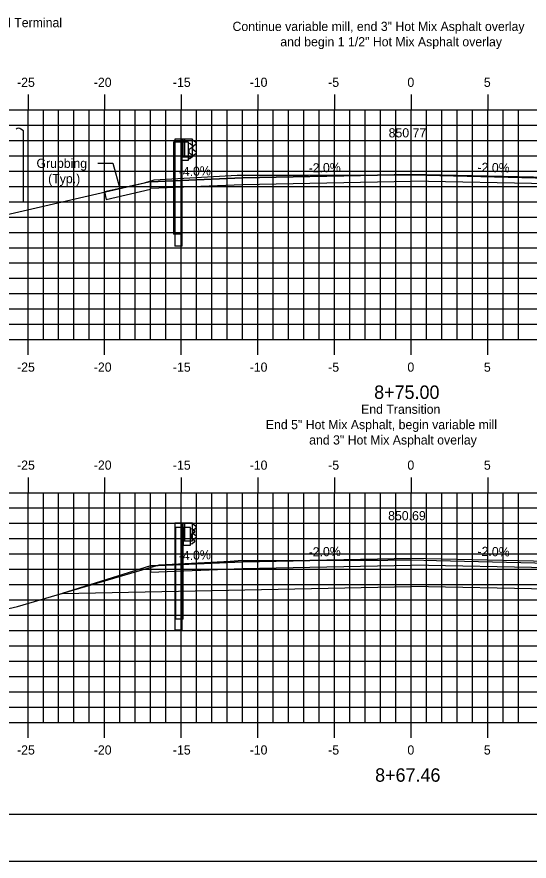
# Model space of a CAD drawing. Extents: x 2194502 to 2194968, y 863888 to 863998.
# Drawn here: x 2194672.8 to 2194706.2, y 863888.4 to 863943.5 of the extents above; entities that cross this region are included whole.
import ezdxf

# ---------------------------------------------------------------- set-up
doc = ezdxf.new("R2010")
doc.units = 0
for name, color, linetype in [('ANNOTATION', 7, 'Continuous'), ('BORDER', 7, 'Continuous'), ('D_Guardrail_Beam_Lt', 7, 'Continuous'), ('D_Guardrail_Beam_Rt', 7, 'Continuous'), ('H_V ANNOTATION', 7, 'Continuous'), ('MAJOR', 7, 'Continuous'), ('MINOR', 7, 'Continuous'), ('PLOT BOUNDARY', 7, 'Continuous'), ('S_Guardrail_Beam', 7, 'Continuous'), ('S_Roadway_Centerline', 7, 'Continuous'), ('S_Utilities_Pole_Power', 7, 'Continuous'), ('TEMPLATE', 7, 'Continuous')]:
    doc.layers.add(name, color=color, linetype=linetype)

msp = doc.modelspace()

# ---------------------------------------------------------------- linework, layer by layer
at = {"layer": 'ANNOTATION'}
msp.add_lwpolyline([(2194678.045, 863933.956), (2194679.045, 863933.956), (2194679.486, 863932.307)], dxfattribs=at)
at = {"layer": 'BORDER'}
msp.add_lwpolyline([(2194623.499, 863891.446), (2194783.499, 863891.446), (2194783.499, 863996.446), (2194623.499, 863996.446)], close=True, dxfattribs=at)
at = {"layer": 'D_Guardrail_Beam_Lt'}
for p, q in [((2194683.07, 863935.542), (2194683.07, 863928.542)), ((2194683.541, 863935.542), (2194683.07, 863935.542)), ((2194684.228, 863935.542), (2194683.541, 863935.542)), ((2194683.541, 863935.542), (2194683.541, 863934.376)), ((2194683.603, 863935.542), (2194683.603, 863934.376)), ((2194683.708, 863935.542), (2194683.708, 863934.376)), ((2194684.228, 863934.376), (2194684.228, 863935.542)), ((2194684.228, 863935.459), (2194684.303, 863935.445)), ((2194684.233, 863934.994), (2194684.233, 863934.924)), ((2194684.462, 863935.195), (2194684.267, 863935.059)), ((2194684.318, 863935.438), (2194684.462, 863935.338)), ((2194683.541, 863934.376), (2194684.228, 863934.376)), ((2194683.562, 863928.542), (2194683.562, 863934.376)), ((2194684.303, 863934.474), (2194684.228, 863934.459)), ((2194684.267, 863934.86), (2194684.462, 863934.723)), ((2194684.462, 863934.58), (2194684.318, 863934.48)), ((2194683.562, 863928.542), (2194683.07, 863928.542))]:
    msp.add_line(p, q, dxfattribs=at)
for centre, major_axis, start_param, end_param in [((2194684.312, 863934.994), (-0.0789, 0), 5.323254, 6.283185), ((2194684.312, 863934.924), (-0.0789, 0), 6.283185, 7.243116), ((2194684.295, 863935.404), (0.0417, 0), 0.959931, 1.376053), ((2194684.412, 863935.266), (0.0877, 0), 5.323254, 7.243116), ((2194684.295, 863934.514), (0.0417, 0), 4.907132, 5.323254), ((2194684.412, 863934.652), (0.0877, 0), 5.323254, 7.243116)]:
    msp.add_ellipse(centre, major_axis=major_axis, ratio=0.995501, start_param=start_param, end_param=end_param, dxfattribs=at)
at = {"layer": 'D_Guardrail_Beam_Rt'}
for p, q in [((2194683.07, 863910.466), (2194683.07, 863903.466)), ((2194683.541, 863910.466), (2194683.07, 863910.466)), ((2194684.228, 863910.466), (2194683.541, 863910.466)), ((2194683.541, 863910.466), (2194683.541, 863909.3)), ((2194683.603, 863910.466), (2194683.603, 863909.3)), ((2194683.708, 863910.466), (2194683.708, 863909.3)), ((2194684.228, 863909.3), (2194684.228, 863910.466)), ((2194684.228, 863910.383), (2194684.303, 863910.368)), ((2194684.462, 863910.119), (2194684.267, 863909.982)), ((2194684.318, 863910.362), (2194684.462, 863910.262)), ((2194684.233, 863909.918), (2194684.233, 863909.848)), ((2194684.267, 863909.783), (2194684.462, 863909.647)), ((2194683.541, 863909.3), (2194684.228, 863909.3)), ((2194683.562, 863903.466), (2194683.562, 863909.3)), ((2194684.303, 863909.397), (2194684.228, 863909.383)), ((2194684.462, 863909.504), (2194684.318, 863909.404)), ((2194683.562, 863903.466), (2194683.07, 863903.466))]:
    msp.add_line(p, q, dxfattribs=at)
for centre, major_axis, start_param, end_param in [((2194684.295, 863910.328), (0.0417, 0), 0.959931, 1.376053), ((2194684.412, 863910.19), (0.0877, 0), 5.323254, 7.243116), ((2194684.312, 863909.918), (-0.0789, 0), 5.323254, 6.283185), ((2194684.312, 863909.848), (-0.0789, 0), 6.283185, 7.243116), ((2194684.412, 863909.576), (0.0877, 0), 5.323254, 7.243116), ((2194684.295, 863909.438), (0.0417, 0), 4.907132, 5.323254)]:
    msp.add_ellipse(centre, major_axis=major_axis, ratio=0.995501, start_param=start_param, end_param=end_param, dxfattribs=at)
at = {"layer": 'MAJOR'}
for p, q in [((2194673.499, 863938.448), (2194673.499, 863937.446)), ((2194678.499, 863938.448), (2194678.499, 863937.446)), ((2194683.499, 863938.448), (2194683.499, 863937.446)), ((2194688.499, 863938.448), (2194688.499, 863937.446)), ((2194693.499, 863938.448), (2194693.499, 863937.446)), ((2194698.499, 863938.448), (2194698.499, 863937.446)), ((2194703.499, 863938.448), (2194703.499, 863937.446)), ((2194628.499, 863937.446), (2194768.499, 863937.446)), ((2194673.499, 863922.446), (2194673.499, 863937.446)), ((2194678.499, 863922.446), (2194678.499, 863937.446)), ((2194683.499, 863922.446), (2194683.499, 863937.446)), ((2194688.499, 863922.446), (2194688.499, 863937.446)), ((2194693.499, 863922.446), (2194693.499, 863937.446)), ((2194698.499, 863922.446), (2194698.499, 863937.446)), ((2194703.499, 863922.446), (2194703.499, 863937.446)), ((2194628.499, 863932.446), (2194768.499, 863932.446)), ((2194628.499, 863927.446), (2194768.499, 863927.446)), ((2194628.499, 863922.446), (2194768.499, 863922.446)), ((2194673.499, 863921.444), (2194673.499, 863922.446)), ((2194678.499, 863921.444), (2194678.499, 863922.446)), ((2194683.499, 863921.444), (2194683.499, 863922.446)), ((2194688.499, 863921.444), (2194688.499, 863922.446)), ((2194693.499, 863921.444), (2194693.499, 863922.446)), ((2194698.499, 863921.444), (2194698.499, 863922.446)), ((2194703.499, 863921.444), (2194703.499, 863922.446)), ((2194673.499, 863913.448), (2194673.499, 863912.446)), ((2194678.499, 863913.448), (2194678.499, 863912.446)), ((2194683.499, 863913.448), (2194683.499, 863912.446)), ((2194688.499, 863913.448), (2194688.499, 863912.446)), ((2194693.499, 863913.448), (2194693.499, 863912.446)), ((2194698.499, 863913.448), (2194698.499, 863912.446)), ((2194703.499, 863913.448), (2194703.499, 863912.446)), ((2194628.499, 863912.446), (2194768.499, 863912.446)), ((2194673.499, 863897.446), (2194673.499, 863912.446)), ((2194678.499, 863897.446), (2194678.499, 863912.446)), ((2194683.499, 863897.446), (2194683.499, 863912.446)), ((2194688.499, 863897.446), (2194688.499, 863912.446)), ((2194693.499, 863897.446), (2194693.499, 863912.446)), ((2194698.499, 863897.446), (2194698.499, 863912.446)), ((2194703.499, 863897.446), (2194703.499, 863912.446)), ((2194628.499, 863907.446), (2194768.499, 863907.446)), ((2194628.499, 863902.446), (2194768.499, 863902.446)), ((2194628.499, 863897.446), (2194768.499, 863897.446)), ((2194673.499, 863896.444), (2194673.499, 863897.446)), ((2194678.499, 863896.444), (2194678.499, 863897.446)), ((2194683.499, 863896.444), (2194683.499, 863897.446)), ((2194688.499, 863896.444), (2194688.499, 863897.446)), ((2194693.499, 863896.444), (2194693.499, 863897.446)), ((2194698.499, 863896.444), (2194698.499, 863897.446)), ((2194703.499, 863896.444), (2194703.499, 863897.446))]:
    msp.add_line(p, q, dxfattribs=at)
at = {"layer": 'MINOR'}
for p, q in [((2194674.499, 863922.446), (2194674.499, 863937.446)), ((2194675.499, 863922.446), (2194675.499, 863937.446)), ((2194676.499, 863922.446), (2194676.499, 863937.446)), ((2194677.499, 863922.446), (2194677.499, 863937.446)), ((2194679.499, 863922.446), (2194679.499, 863937.446)), ((2194680.499, 863922.446), (2194680.499, 863937.446)), ((2194681.499, 863922.446), (2194681.499, 863937.446)), ((2194682.499, 863922.446), (2194682.499, 863937.446)), ((2194684.499, 863922.446), (2194684.499, 863937.446)), ((2194685.499, 863922.446), (2194685.499, 863937.446)), ((2194686.499, 863922.446), (2194686.499, 863937.446)), ((2194687.499, 863922.446), (2194687.499, 863937.446)), ((2194689.499, 863922.446), (2194689.499, 863937.446)), ((2194690.499, 863922.446), (2194690.499, 863937.446)), ((2194691.499, 863922.446), (2194691.499, 863937.446)), ((2194692.499, 863922.446), (2194692.499, 863937.446)), ((2194694.499, 863922.446), (2194694.499, 863937.446)), ((2194695.499, 863922.446), (2194695.499, 863937.446)), ((2194696.499, 863922.446), (2194696.499, 863937.446)), ((2194697.499, 863922.446), (2194697.499, 863937.446)), ((2194699.499, 863922.446), (2194699.499, 863937.446)), ((2194700.499, 863922.446), (2194700.499, 863937.446)), ((2194701.499, 863922.446), (2194701.499, 863937.446)), ((2194702.499, 863922.446), (2194702.499, 863937.446)), ((2194704.499, 863922.446), (2194704.499, 863937.446)), ((2194705.499, 863922.446), (2194705.499, 863937.446)), ((2194628.499, 863936.446), (2194768.499, 863936.446)), ((2194628.499, 863935.446), (2194768.499, 863935.446)), ((2194628.499, 863934.446), (2194768.499, 863934.446)), ((2194628.499, 863933.446), (2194768.499, 863933.446)), ((2194628.499, 863931.446), (2194768.499, 863931.446)), ((2194628.499, 863930.446), (2194768.499, 863930.446)), ((2194628.499, 863929.446), (2194768.499, 863929.446)), ((2194628.499, 863928.446), (2194768.499, 863928.446)), ((2194628.499, 863926.446), (2194768.499, 863926.446)), ((2194628.499, 863925.446), (2194768.499, 863925.446)), ((2194628.499, 863924.446), (2194768.499, 863924.446)), ((2194628.499, 863923.446), (2194768.499, 863923.446)), ((2194674.499, 863897.446), (2194674.499, 863912.446)), ((2194675.499, 863897.446), (2194675.499, 863912.446)), ((2194676.499, 863897.446), (2194676.499, 863912.446)), ((2194677.499, 863897.446), (2194677.499, 863912.446)), ((2194679.499, 863897.446), (2194679.499, 863912.446)), ((2194680.499, 863897.446), (2194680.499, 863912.446)), ((2194681.499, 863897.446), (2194681.499, 863912.446)), ((2194682.499, 863897.446), (2194682.499, 863912.446)), ((2194684.499, 863897.446), (2194684.499, 863912.446)), ((2194685.499, 863897.446), (2194685.499, 863912.446)), ((2194686.499, 863897.446), (2194686.499, 863912.446)), ((2194687.499, 863897.446), (2194687.499, 863912.446)), ((2194689.499, 863897.446), (2194689.499, 863912.446)), ((2194690.499, 863897.446), (2194690.499, 863912.446)), ((2194691.499, 863897.446), (2194691.499, 863912.446)), ((2194692.499, 863897.446), (2194692.499, 863912.446)), ((2194694.499, 863897.446), (2194694.499, 863912.446)), ((2194695.499, 863897.446), (2194695.499, 863912.446)), ((2194696.499, 863897.446), (2194696.499, 863912.446)), ((2194697.499, 863897.446), (2194697.499, 863912.446)), ((2194699.499, 863897.446), (2194699.499, 863912.446)), ((2194700.499, 863897.446), (2194700.499, 863912.446)), ((2194701.499, 863897.446), (2194701.499, 863912.446)), ((2194702.499, 863897.446), (2194702.499, 863912.446)), ((2194704.499, 863897.446), (2194704.499, 863912.446)), ((2194705.499, 863897.446), (2194705.499, 863912.446)), ((2194628.499, 863911.446), (2194768.499, 863911.446)), ((2194628.499, 863910.446), (2194768.499, 863910.446)), ((2194628.499, 863909.446), (2194768.499, 863909.446)), ((2194628.499, 863908.446), (2194768.499, 863908.446)), ((2194628.499, 863906.446), (2194768.499, 863906.446)), ((2194628.499, 863905.446), (2194768.499, 863905.446)), ((2194628.499, 863904.446), (2194768.499, 863904.446)), ((2194628.499, 863903.446), (2194768.499, 863903.446)), ((2194628.499, 863901.446), (2194768.499, 863901.446)), ((2194628.499, 863900.446), (2194768.499, 863900.446)), ((2194628.499, 863899.446), (2194768.499, 863899.446)), ((2194628.499, 863898.446), (2194768.499, 863898.446))]:
    msp.add_line(p, q, dxfattribs=at)
at = {"layer": 'PLOT BOUNDARY'}
msp.add_lwpolyline([(2194615.406, 863888.387), (2194785.406, 863888.387), (2194785.406, 863998.387), (2194615.406, 863998.387)], close=True, dxfattribs=at)
at = {"layer": 'S_Guardrail_Beam'}
for p, q in [((2194682.997, 863935.335), (2194682.997, 863929.335)), ((2194683.489, 863935.335), (2194682.997, 863935.335)), ((2194683.978, 863935.335), (2194683.489, 863935.335)), ((2194683.489, 863935.335), (2194683.489, 863934.168)), ((2194683.978, 863934.168), (2194683.978, 863935.335)), ((2194683.978, 863935.262), (2194684.06, 863935.248)), ((2194684.22, 863934.998), (2194684.025, 863934.861)), ((2194684.077, 863935.241), (2194684.22, 863935.141)), ((2194683.991, 863934.797), (2194683.991, 863934.706)), ((2194684.025, 863934.642), (2194684.22, 863934.506)), ((2194683.489, 863929.335), (2194683.489, 863934.168)), ((2194683.489, 863934.168), (2194683.978, 863934.168)), ((2194684.06, 863934.256), (2194683.978, 863934.241)), ((2194684.22, 863934.362), (2194684.077, 863934.262)), ((2194683.489, 863929.335), (2194682.997, 863929.335)), ((2194683.127, 863910.179), (2194683.127, 863904.179)), ((2194683.619, 863910.179), (2194683.127, 863910.179)), ((2194684.108, 863910.179), (2194683.619, 863910.179)), ((2194683.619, 863910.179), (2194683.619, 863909.012)), ((2194684.108, 863909.012), (2194684.108, 863910.179)), ((2194684.108, 863910.106), (2194684.191, 863910.091)), ((2194684.122, 863909.641), (2194684.122, 863909.55)), ((2194684.351, 863909.842), (2194684.155, 863909.705)), ((2194684.207, 863910.085), (2194684.351, 863909.985)), ((2194683.619, 863904.179), (2194683.619, 863909.012)), ((2194683.619, 863909.012), (2194684.108, 863909.012)), ((2194684.191, 863909.099), (2194684.108, 863909.085)), ((2194684.155, 863909.486), (2194684.351, 863909.349)), ((2194684.351, 863909.206), (2194684.207, 863909.106)), ((2194683.619, 863904.179), (2194683.127, 863904.179))]:
    msp.add_line(p, q, dxfattribs=at)
for centre, major_axis, start_param, end_param in [((2194684.053, 863935.207), (0.0417, 0), 0.959931, 1.396263), ((2194684.17, 863935.069), (0.0877, 0), 5.323254, 7.243116), ((2194684.07, 863934.797), (-0.0789, 0), 5.323254, 6.283185), ((2194684.07, 863934.706), (-0.0789, 0), 6.283185, 7.243116), ((2194684.17, 863934.434), (0.0877, 0), 5.323254, 7.243116), ((2194684.053, 863934.296), (0.0417, 0), 4.886922, 5.323254), ((2194684.201, 863909.641), (-0.0789, 0), 5.323254, 6.283185), ((2194684.183, 863910.051), (0.0417, 0), 0.959931, 1.396263), ((2194684.3, 863909.913), (0.0877, 0), 5.323254, 7.243116), ((2194684.201, 863909.55), (-0.0789, 0), 6.283185, 7.243116), ((2194684.183, 863909.14), (0.0417, 0), 4.886922, 5.323254), ((2194684.3, 863909.278), (0.0877, 0), 5.323254, 7.243116)]:
    msp.add_ellipse(centre, major_axis=major_axis, ratio=0.995501, start_param=start_param, end_param=end_param, dxfattribs=at)
at = {"layer": 'S_Roadway_Centerline'}
for points in [[(2194628.499, 863931.248), (2194644.102, 863931.812), (2194651.913, 863930.949), (2194668.077, 863929.672), (2194681.104, 863932.691), (2194681.74, 863932.878), (2194687.144, 863933.179), (2194687.162, 863933.181), (2194691.811, 863933.191), (2194698.499, 863933.212), (2194698.585, 863933.211), (2194710.18, 863932.915), (2194712.278, 863932.755), (2194712.76, 863932.719), (2194712.774, 863932.719), (2194718.053, 863932.454), (2194719.251, 863932.444), (2194722.99, 863932.169), (2194730.529, 863930.489), (2194735.351, 863929.559), (2194737.618, 863928.913), (2194750.8, 863926.104), (2194768.499, 863925.832)], [(2194667.598, 863903.809), (2194672.818, 863905.013), (2194682.058, 863907.726), (2194686.684, 863907.983), (2194687.208, 863908.025), (2194696.988, 863908.045), (2194698.48, 863908.066), (2194700.167, 863908.027), (2194710.222, 863907.77), (2194710.933, 863907.72), (2194713.063, 863907.563), (2194714.672, 863907.54), (2194718.844, 863907.33), (2194723.196, 863907.293), (2194725.536, 863907.121), (2194734.215, 863905.192), (2194736.558, 863903.65), (2194738.492, 863903.278), (2194745.923, 863901.819), (2194754.026, 863901.226), (2194762.901, 863901.073), (2194768.499, 863901.043)]]:
    msp.add_lwpolyline(points, dxfattribs=at)
at = {"layer": 'S_Utilities_Pole_Power'}
for p, q in [((2194673.195, 863936.084), (2194673.039, 863936.194)), ((2194673.195, 863931.464), (2194673.198, 863936.084))]:
    msp.add_line(p, q, dxfattribs=at)
for start, end in [(90, 125.2644), (54.7356, 90)]:
    msp.add_arc((2194672.882, 863935.973), 0.271, start, end, dxfattribs=at)
at = {"layer": 'TEMPLATE'}
for p, q in [((2194681.499, 863932.756), (2194678.499, 863932.088)), ((2194687.499, 863932.996), (2194681.499, 863932.756)), ((2194687.499, 863932.996), (2194698.499, 863933.216)), ((2194698.499, 863933.216), (2194687.499, 863932.996)), ((2194687.499, 863932.579), (2194698.499, 863932.799)), ((2194709.499, 863932.996), (2194698.499, 863933.216)), ((2194709.499, 863932.579), (2194698.499, 863932.799)), ((2194678.499, 863932.088), (2194678.608, 863931.6)), ((2194687.499, 863907.92), (2194681.499, 863907.68)), ((2194687.499, 863907.92), (2194698.499, 863908.14)), ((2194698.499, 863908.14), (2194687.499, 863907.92)), ((2194709.499, 863907.92), (2194698.499, 863908.14)), ((2194681.499, 863907.68), (2194675.727, 863905.867)), ((2194687.499, 863907.503), (2194698.499, 863907.723)), ((2194709.499, 863907.503), (2194698.499, 863907.723)), ((2194675.727, 863905.867), (2194698.499, 863906.323)), ((2194708.499, 863906.123), (2194698.499, 863906.323))]:
    msp.add_line(p, q, dxfattribs=at)
for points in [[(2194681.499, 863932.756), (2194681.499, 863932.756), (2194687.499, 863932.996)], [(2194681.499, 863932.339), (2194681.499, 863932.756), (2194681.499, 863932.339), (2194687.499, 863932.579)], [(2194678.608, 863931.6), (2194681.499, 863932.27), (2194681.499, 863932.339)], [(2194681.499, 863907.68), (2194681.499, 863907.68), (2194687.499, 863907.92)], [(2194681.499, 863907.263), (2194681.499, 863907.68), (2194681.499, 863907.263), (2194687.499, 863907.503)]]:
    msp.add_lwpolyline(points, dxfattribs=at)

# ---------------------------------------------------------------- texts
at = {"layer": 'ANNOTATION'}
for s, p in [('Install 31" W-Beam Guardrail, Mid-Way Splice Flared Terminal', (2194653.499, 863942.844)), ('Continue variable mill, end 3" Hot Mix Asphalt overlay', (2194686.845, 863942.596)), ('and begin 1 1/2" Hot Mix Asphalt overlay', (2194689.963, 863941.594)), ('850.77', (2194697.033, 863935.646)), ('Grubbing', (2194674.052, 863933.656)), ('(Typ.)', (2194674.812, 863932.654)), ('End Transition', (2194695.236, 863917.596)), ('End 5" Hot Mix Asphalt, begin variable mill', (2194689.018, 863916.594)), ('and 3" Hot Mix Asphalt overlay', (2194691.846, 863915.592)), ('850.69', (2194697.001, 863910.646))]:
    msp.add_text(s, height=0.6, dxfattribs=at).set_placement(p)
for s, rotation, p in [('-2.0%', 1.1458, (2194691.817, 863933.349)), ('-2.0%', 358.8542, (2194702.828, 863933.396)), ('-4.0%', 2.2906, (2194683.344, 863933.097)), ('-4.0%', 2.2906, (2194683.344, 863908.02)), ('-2.0%', 1.1458, (2194691.817, 863908.273)), ('-2.0%', 358.8542, (2194702.828, 863908.32))]:
    msp.add_text(s, height=0.6, rotation=rotation, dxfattribs=at).set_placement(p)
at = {"layer": 'H_V ANNOTATION'}
for s, height, p in [('-25', 0.6, (2194672.785, 863938.946)), ('-20', 0.6, (2194677.793, 863938.946)), ('-15', 0.6, (2194682.956, 863938.946)), ('-10', 0.6, (2194687.964, 863938.946)), ('-5', 0.6, (2194693.09, 863938.946)), ('0', 0.6, (2194698.258, 863938.946)), ('5', 0.6, (2194703.25, 863938.946)), ('-25', 0.6, (2194672.785, 863920.346)), ('-20', 0.6, (2194677.793, 863920.346)), ('-15', 0.6, (2194682.956, 863920.346)), ('-10', 0.6, (2194687.964, 863920.346)), ('-5', 0.6, (2194693.09, 863920.346)), ('0', 0.6, (2194698.258, 863920.346)), ('5', 0.6, (2194703.25, 863920.346)), ('8+75.00', 0.875, (2194696.088, 863918.571)), ('-25', 0.6, (2194672.785, 863913.946)), ('-20', 0.6, (2194677.793, 863913.946)), ('-15', 0.6, (2194682.956, 863913.946)), ('-10', 0.6, (2194687.964, 863913.946)), ('-5', 0.6, (2194693.09, 863913.946)), ('0', 0.6, (2194698.258, 863913.946)), ('5', 0.6, (2194703.25, 863913.946)), ('-25', 0.6, (2194672.785, 863895.346)), ('-20', 0.6, (2194677.793, 863895.346)), ('-15', 0.6, (2194682.956, 863895.346)), ('-10', 0.6, (2194687.964, 863895.346)), ('-5', 0.6, (2194693.09, 863895.346)), ('0', 0.6, (2194698.258, 863895.346)), ('5', 0.6, (2194703.25, 863895.346)), ('8+67.46', 0.875, (2194696.151, 863893.571))]:
    msp.add_text(s, height=height, dxfattribs=at).set_placement(p)

doc.saveas('drawing.dxf')
